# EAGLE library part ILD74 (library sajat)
SIEMENS OPTO COUPLER
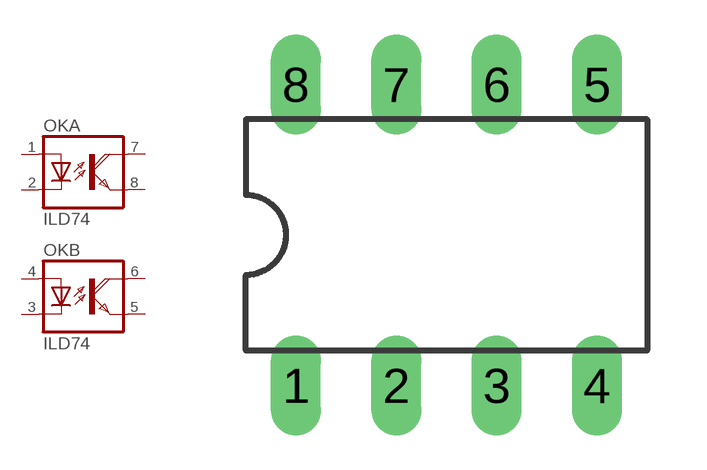
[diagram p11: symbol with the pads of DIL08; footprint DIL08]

Designator prefix OK; gates A=OK-D B=OK-D

## ILD74  [DIL08]
1  A:A  pas
2  A:C  pas
3  B:C  pas
4  B:A  pas
5  B:EMI  pas
6  B:COL  pas
7  A:COL  pas
8  A:EMI  pas

## Footprint DIL08 (pad centres in mm)
Dual In Line Package
drill 0.5 pad 1.27 long: 1 -3.81,-3.81; 2 -1.27,-3.81; 3 1.27,-3.81; 4 3.81,-3.81; 5 3.81,3.81; 6 1.27,3.81; 7 -1.27,3.81; 8 -3.81,3.81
